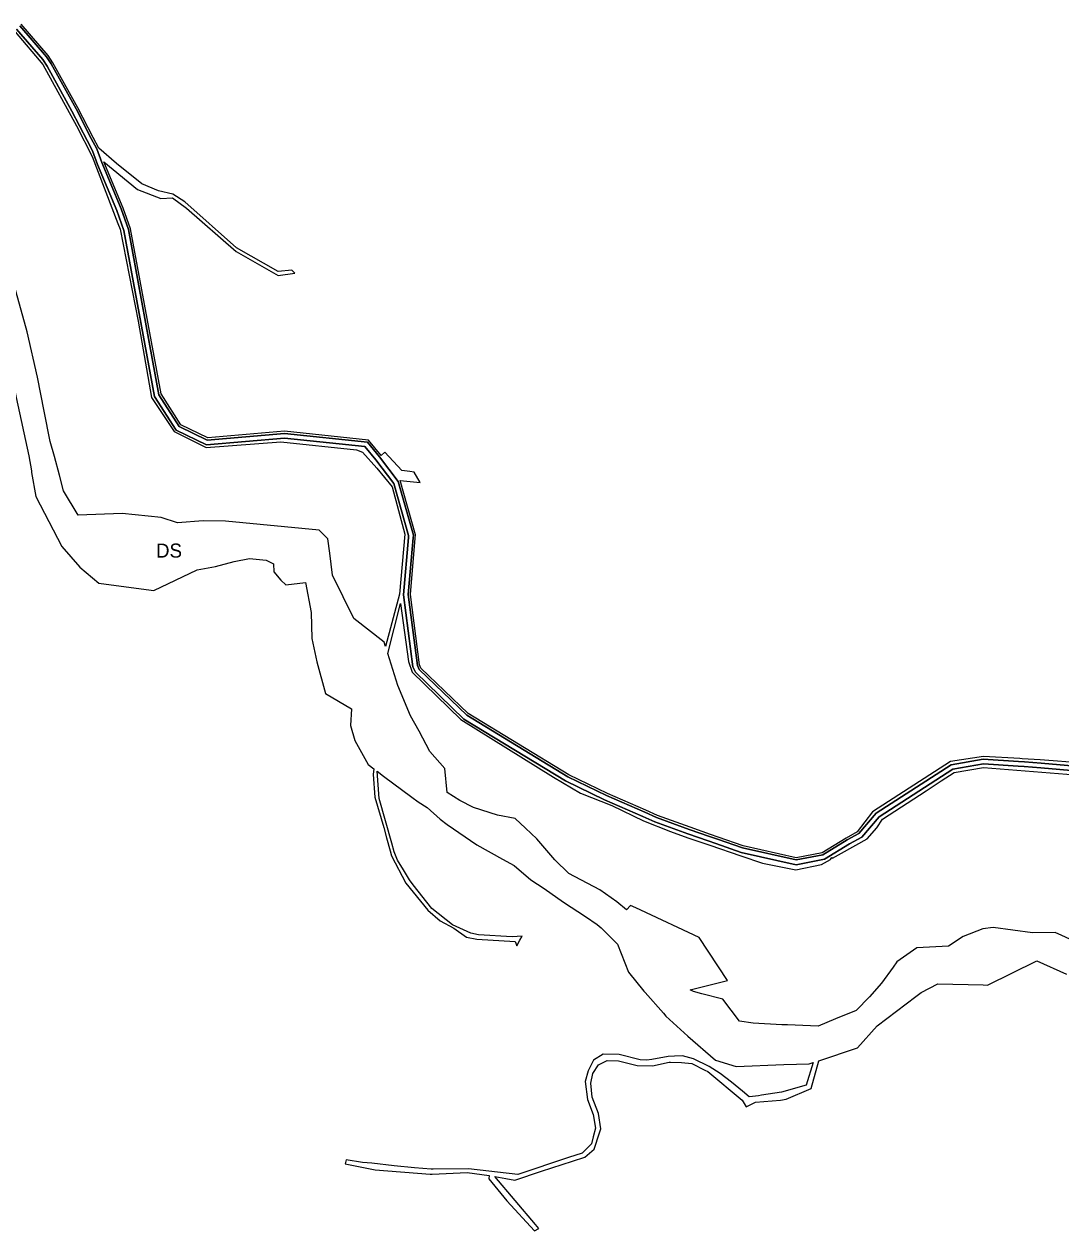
# Model space of a CAD drawing. Extents: x -477304 to -465641, y -1159113 to -1149285.
# Drawn here: x -476638 to -475972, y -1151586 to -1150812 of the extents above; entities that cross this region are included whole.
import ezdxf

# ---------------------------------------------------------------- set-up
doc = ezdxf.new("R2010")
doc.units = 0
doc.layers.add('14', color=7, linetype='Continuous')
doc.layers.add('35', color=7, linetype='Continuous')

msp = doc.modelspace()

# ---------------------------------------------------------------- linework, layer by layer
at = {"layer": '14'}
for points in [[(-476642.66, -1150814.82), (-476625.91, -1150834.23), (-476623.17, -1150838.54), (-476607.19, -1150867.39), (-476597.42, -1150886.27), (-476594.01, -1150892.86), (-476590.76, -1150901.49), (-476578.3, -1150931.21), (-476573.77, -1150944.02), (-476554.16, -1151050.43), (-476540.35, -1151072.15), (-476520.85, -1151081.51), (-476470.75, -1151077.16), (-476419.11, -1151082.62), (-476412.19, -1151090.99), (-476400.56, -1151106.27), (-476391.07, -1151139.73), (-476391.18, -1151140.91), (-476394.41, -1151177.66), (-476388.4, -1151223.93), (-476386.78, -1151227.31), (-476355.62, -1151257.4), (-476290.4, -1151297.08), (-476265.36, -1151309.27), (-476240.73, -1151319.97), (-476233.05, -1151323.47), (-476211.94, -1151331.01), (-476198.89, -1151335.55), (-476193.95, -1151337.27), (-476177.68, -1151342.98), (-476142.48, -1151350.92), (-476124.11, -1151347.34), (-476108.09, -1151337.56), (-476100.22, -1151333.1), (-476089.09, -1151320.18), (-476041.78, -1151289.56), (-476022.14, -1151286.25), (-475999.9, -1151287.63), (-475996.05, -1151287.84), (-475985.31, -1151288.74), (-475953.69, -1151291.49)], [(-475953.31, -1151288.51), (-475985.05, -1151285.75), (-475995.85, -1151284.85), (-475999.73, -1151284.64), (-476022.3, -1151283.24), (-476042.89, -1151286.71), (-476091.09, -1151317.9), (-476102.15, -1151330.75), (-476109.61, -1151334.97), (-476125.22, -1151344.5), (-476142.43, -1151347.85), (-476176.85, -1151340.09), (-476192.96, -1151334.44), (-476197.91, -1151332.72), (-476210.94, -1151328.18), (-476231.92, -1151320.68), (-476239.51, -1151317.23), (-476264.1, -1151306.55), (-476288.96, -1151294.44), (-476353.78, -1151255.01), (-476384.31, -1151225.53), (-476385.48, -1151223.07), (-476391.39, -1151177.6), (-476388.19, -1151141.18), (-476388.03, -1151139.44), (-476397.83, -1151104.9), (-476409.84, -1151089.13), (-476417.58, -1151079.77), (-476470.72, -1151074.15), (-476520.29, -1151078.45), (-476538.28, -1151069.81), (-476551.31, -1151049.31), (-476570.86, -1150943.24), (-476575.5, -1150930.13), (-476587.98, -1150900.39), (-476591.27, -1150891.64), (-476594.76, -1150884.89), (-476604.55, -1150865.98), (-476620.59, -1150837), (-476623.5, -1150832.43), (-476640.64, -1150812.58)]]:
    msp.add_lwpolyline(points, dxfattribs=at)
at = {"layer": '35'}
for p, q in [((-476622.38, -1150831.6), (-476639.7, -1150811.53)), ((-476643.54, -1150816.44), (-476625.93, -1150837.46)), ((-476619.39, -1150836.29), (-476622.38, -1150831.6)), ((-476625.93, -1150837.46), (-476604.19, -1150876.72)), ((-476603.32, -1150865.32), (-476619.39, -1150836.29)), ((-476593.52, -1150884.25), (-476603.32, -1150865.32)), ((-476589.99, -1150891.07), (-476593.52, -1150884.25)), ((-476578.66, -1150901.01), (-476589.99, -1150891.07)), ((-476574.2, -1150929.63), (-476586.68, -1150899.87)), ((-476586.68, -1150899.87), (-476565.05, -1150917.63)), ((-476562.32, -1150914.04), (-476578.66, -1150901.01)), ((-476565.05, -1150917.63), (-476550.04, -1150923.44)), ((-476534.64, -1150925.58), (-476542.51, -1150920.67)), ((-476474.84, -1150972.71), (-476464.02, -1150971.38)), ((-476466.14, -1150969.46), (-476474.78, -1150970.34)), ((-476464.02, -1150971.38), (-476466.14, -1150969.46)), ((-476556.1, -1151051.13), (-476541.51, -1151072.81)), ((-476537.32, -1151068.73), (-476549.99, -1151048.79)), ((-476541.51, -1151072.81), (-476520.92, -1151083.15)), ((-476520.03, -1151077.03), (-476537.32, -1151068.73)), ((-476470.71, -1151072.75), (-476520.03, -1151077.03)), ((-476416.87, -1151078.44), (-476470.71, -1151072.75)), ((-476520.92, -1151083.15), (-476473.05, -1151079.6)), ((-476473.05, -1151079.6), (-476424.55, -1151084.62)), ((-476408.75, -1151088.26), (-476416.87, -1151078.44)), ((-476634.92, -1151088.51), (-476633.21, -1151098.11)), ((-476424.55, -1151084.62), (-476420.69, -1151086.09)), ((-476420.69, -1151086.09), (-476411.49, -1151096.46)), ((-476406.46, -1151086.27), (-476408.75, -1151088.26)), ((-476395.44, -1151097.97), (-476406.46, -1151086.27)), ((-476633.21, -1151098.11), (-476633.02, -1151099.3)), ((-476411.49, -1151096.46), (-476401.66, -1151108.45)), ((-476390.38, -1151098.59), (-476395.44, -1151097.97)), ((-476396.56, -1151104.27), (-476383.64, -1151105.71)), ((-476387.56, -1151099.04), (-476390.38, -1151098.59)), ((-476383.64, -1151105.71), (-476387.56, -1151099.04)), ((-476574.84, -1151125.55), (-476603.1, -1151126.52)), ((-476441.63, -1151150.91), (-476443.04, -1151141.85)), ((-476439.9, -1151165.06), (-476441.63, -1151150.91)), ((-476554.67, -1151174.97), (-476526.86, -1151161.65)), ((-476477.6, -1151162.96), (-476473.1, -1151168.36)), ((-476426.36, -1151192.97), (-476439.9, -1151165.06)), ((-476396.99, -1151177.28), (-476405.87, -1151210.97)), ((-476404.5, -1151215.31), (-476396.2, -1151183.22)), ((-476396.2, -1151183.22), (-476391.22, -1151220.46)), ((-476398, -1151235.98), (-476404.5, -1151215.31)), ((-476383.16, -1151224.7), (-476384.13, -1151222.67)), ((-476352.92, -1151253.9), (-476383.16, -1151224.7)), ((-476288.29, -1151293.22), (-476352.92, -1151253.9)), ((-476428.34, -1151261.66), (-476425.69, -1151271.16)), ((-476377.58, -1151278.27), (-476384.43, -1151265.14)), ((-475985.84, -1151283.58), (-475997.32, -1151282.86)), ((-475958.11, -1151285.78), (-475985.84, -1151283.58)), ((-476413.42, -1151289.39), (-476413.77, -1151292.95)), ((-476410.09, -1151308.46), (-476411.36, -1151290.95)), ((-476263.52, -1151305.28), (-476288.29, -1151293.22)), ((-476059.04, -1151303.43), (-476049.41, -1151297.03)), ((-476049.41, -1151297.03), (-476041.07, -1151291.81)), ((-476086.94, -1151321.74), (-476059.04, -1151303.43)), ((-476401.85, -1151337.16), (-476410.09, -1151308.46)), ((-476385.07, -1151310.45), (-476379.17, -1151314.22)), ((-476379.17, -1151314.22), (-476370.84, -1151321.76)), ((-476316.03, -1151327.52), (-476322.68, -1151321.3)), ((-476240.43, -1151322.7), (-476223, -1151329.58)), ((-476093.34, -1151316.86), (-476103.13, -1151329.7)), ((-476090.63, -1151327.32), (-476086.94, -1151321.74)), ((-476407, -1151327.11), (-476405.24, -1151333.64)), ((-476223, -1151329.58), (-476211.87, -1151333.69)), ((-476103.13, -1151329.7), (-476110.32, -1151333.77)), ((-476096.81, -1151334.23), (-476090.63, -1151327.32)), ((-476400.45, -1151342.69), (-476401.85, -1151337.16)), ((-476347.32, -1151338.15), (-476330.92, -1151347.31)), ((-476176.46, -1151338.75), (-476192.5, -1151333.12)), ((-476110.32, -1151333.77), (-476125.73, -1151343.18)), ((-476113.38, -1151343.53), (-476096.81, -1151334.23)), ((-476402.11, -1151345.22), (-476392.86, -1151362.69)), ((-476398.2, -1151348.06), (-476400.45, -1151342.69)), ((-476177.91, -1151345.12), (-476164.06, -1151349.82)), ((-476118.96, -1151346.66), (-476113.38, -1151343.53)), ((-476394.48, -1151354.09), (-476398.2, -1151348.06)), ((-476330.92, -1151347.31), (-476323.3, -1151351.3)), ((-476288.27, -1151356.51), (-476297.23, -1151347.85)), ((-476126.17, -1151350.72), (-476120.34, -1151347.44)), ((-476120.34, -1151347.44), (-476119.45, -1151346.29)), ((-476119.45, -1151346.29), (-476118.96, -1151346.66)), ((-476390.45, -1151360.63), (-476394.48, -1151354.09)), ((-476388.16, -1151363.74), (-476390.45, -1151360.63)), ((-476268.39, -1151367.02), (-476288.27, -1151356.51)), ((-476392.86, -1151362.69), (-476378.85, -1151380.09)), ((-476376.2, -1151379), (-476388.16, -1151363.74)), ((-476257.41, -1151374.76), (-476268.39, -1151367.02)), ((-476251.27, -1151379.83), (-476257.41, -1151374.76)), ((-476378.85, -1151380.09), (-476370.78, -1151386.79)), ((-476204.63, -1151397.52), (-476241.99, -1151380.13)), ((-476370.78, -1151386.79), (-476362.02, -1151391.51)), ((-476362.02, -1151391.51), (-476353.92, -1151397.38)), ((-476269.99, -1151389.31), (-476267.58, -1151391.48)), ((-476267.58, -1151391.48), (-476256.99, -1151401.96)), ((-476022.58, -1151392.02), (-476035.16, -1151397.04)), ((-476015.93, -1151391.11), (-476022.58, -1151392.02)), ((-475990.68, -1151394.51), (-476015.93, -1151391.11)), ((-476353.92, -1151397.38), (-476347.4, -1151398.62)), ((-476346.23, -1151395.92), (-476351.16, -1151394.79)), ((-476347.4, -1151398.62), (-476322.81, -1151400.15)), ((-476324.71, -1151397.09), (-476346.23, -1151395.92)), ((-476318.23, -1151396.75), (-476324.71, -1151397.09)), ((-476322.81, -1151400.15), (-476321.73, -1151402.9)), ((-476321.73, -1151402.9), (-476319.71, -1151399.32)), ((-476319.71, -1151399.32), (-476318.23, -1151396.75)), ((-476186.54, -1151425.18), (-476204.63, -1151397.52)), ((-476035.16, -1151397.04), (-476044.6, -1151403.16)), ((-475976.2, -1151394.31), (-475990.68, -1151394.51)), ((-476044.6, -1151403.16), (-476064.85, -1151404.13)), ((-476019.56, -1151428.19), (-475987.82, -1151412.6)), ((-475987.82, -1151412.6), (-475968.79, -1151421.19)), ((-476080.18, -1151416.71), (-476087.65, -1151426.89)), ((-476210.37, -1151431.1), (-476186.54, -1151425.18)), ((-476087.65, -1151426.89), (-476095.31, -1151435.71)), ((-476062.2, -1151432.93), (-476051.5, -1151427.33)), ((-476051.5, -1151427.33), (-476022.39, -1151428.01)), ((-476022.39, -1151428.01), (-476019.56, -1151428.19)), ((-476239.19, -1151432.96), (-476227.53, -1151446.2)), ((-476095.31, -1151435.71), (-476103.94, -1151444.53)), ((-476090.46, -1151454.27), (-476065.48, -1151435.34)), ((-476065.48, -1151435.34), (-476062.2, -1151432.93)), ((-476227.53, -1151446.2), (-476226.06, -1151447.98)), ((-476226.06, -1151447.98), (-476211.83, -1151460.99)), ((-476147.99, -1151453.67), (-476151.51, -1151453.53)), ((-476103.12, -1151468.47), (-476090.46, -1151454.27)), ((-476211.83, -1151460.99), (-476194.04, -1151476.2)), ((-476127.89, -1151476.65), (-476103.12, -1151468.47)), ((-476256.05, -1151472.57), (-476266.21, -1151472.52)), ((-476208.33, -1151475.52), (-476215.41, -1151473.57)), ((-476198.28, -1151480.3), (-476208.33, -1151475.52)), ((-476194.04, -1151476.2), (-476180.86, -1151480.43)), ((-476275.76, -1151483.15), (-476277.8, -1151489.9)), ((-476200.95, -1151482.78), (-476199.05, -1151483.55)), ((-476199.05, -1151483.55), (-476176.95, -1151501.92)), ((-476277.8, -1151489.9), (-476276.37, -1151501.52)), ((-476273.25, -1151499.95), (-476274.2, -1151490.98)), ((-476176.8, -1151496.23), (-476183.89, -1151490.43)), ((-476269.33, -1151510.54), (-476273.25, -1151499.95)), ((-476172.47, -1151499.83), (-476176.8, -1151496.23)), ((-476170.33, -1151499.57), (-476172.47, -1151499.83)), ((-476151.85, -1151496.93), (-476164.64, -1151498.74)), ((-476276.37, -1151501.52), (-476272.64, -1151511.14)), ((-476176.95, -1151501.92), (-476174.52, -1151506.3)), ((-476174.52, -1151506.3), (-476168.48, -1151503.29)), ((-476168.48, -1151503.29), (-476152.35, -1151501.95)), ((-476152.35, -1151501.95), (-476148.83, -1151501.25)), ((-476273.68, -1151530), (-476279.66, -1151535.9)), ((-476272.55, -1151525.56), (-476273.68, -1151530)), ((-476288.41, -1151538.81), (-476320.96, -1151549.65)), ((-476279.66, -1151535.9), (-476288.41, -1151538.81)), ((-476285.88, -1151541.09), (-476277.94, -1151538.48)), ((-476431.07, -1151540.31), (-476431.91, -1151542.86)), ((-476431.91, -1151542.86), (-476412.65, -1151546.62)), ((-476400.35, -1151544.17), (-476414.78, -1151542.4)), ((-476412.65, -1151546.62), (-476377.17, -1151549.4)), ((-476387.24, -1151545.36), (-476400.35, -1151544.17)), ((-476376.66, -1151546.28), (-476387.24, -1151545.36)), ((-476375.28, -1151546.27), (-476376.66, -1151546.28)), ((-476352.56, -1151546.07), (-476375.28, -1151546.27)), ((-476320.96, -1151549.65), (-476352.56, -1151546.07)), ((-476377.17, -1151549.4), (-476375.97, -1151549.35)), ((-476375.97, -1151549.35), (-476353.46, -1151548.47)), ((-476353.46, -1151548.47), (-476339.44, -1151550.28)), ((-476339.44, -1151550.28), (-476339.71, -1151552.33)), ((-476339.71, -1151552.33), (-476327.96, -1151566.52)), ((-476335.79, -1151551), (-476328.8, -1151552.22)), ((-476328.8, -1151552.22), (-476322.91, -1151553.24)), ((-476327.96, -1151566.52), (-476310.28, -1151585.82)), ((-476310.28, -1151585.82), (-476307.47, -1151584.26))]:
    msp.add_line(p, q, dxfattribs=at)
for points in [[(-475953.69, -1151291.49), (-475985.31, -1151288.74), (-475996.05, -1151287.84), (-475999.9, -1151287.63), (-476022.14, -1151286.25), (-476041.78, -1151289.56), (-476089.09, -1151320.18), (-476100.22, -1151333.1), (-476108.09, -1151337.56), (-476124.11, -1151347.34), (-476142.48, -1151350.92), (-476177.68, -1151342.98), (-476193.95, -1151337.27), (-476198.89, -1151335.55), (-476211.94, -1151331.01), (-476233.05, -1151323.47), (-476240.73, -1151319.97), (-476265.36, -1151309.27), (-476290.4, -1151297.08), (-476355.62, -1151257.4), (-476386.78, -1151227.31), (-476388.4, -1151223.93), (-476394.41, -1151177.66), (-476391.18, -1151140.91), (-476391.07, -1151139.73), (-476400.56, -1151106.27), (-476412.19, -1151090.99), (-476419.11, -1151082.62), (-476470.75, -1151077.16), (-476520.85, -1151081.51), (-476540.35, -1151072.15), (-476554.16, -1151050.43), (-476573.77, -1150944.02), (-476578.3, -1150931.21), (-476590.76, -1150901.49), (-476594.01, -1150892.86), (-476597.42, -1150886.27), (-476607.19, -1150867.39), (-476623.17, -1150838.54), (-476625.91, -1150834.23), (-476642.66, -1150814.82)], [(-476640.64, -1150812.58), (-476623.5, -1150832.43), (-476620.59, -1150837), (-476604.55, -1150865.98), (-476594.76, -1150884.89), (-476591.27, -1150891.64), (-476587.98, -1150900.39), (-476575.5, -1150930.13), (-476570.86, -1150943.24), (-476551.31, -1151049.31), (-476538.28, -1151069.81), (-476520.29, -1151078.45), (-476470.72, -1151074.15), (-476417.58, -1151079.77), (-476409.84, -1151089.13), (-476397.83, -1151104.9), (-476388.03, -1151139.44), (-476388.19, -1151141.18), (-476391.39, -1151177.6), (-476385.48, -1151223.07), (-476384.31, -1151225.53), (-476353.78, -1151255.01), (-476288.96, -1151294.44), (-476264.1, -1151306.55), (-476239.51, -1151317.23), (-476231.92, -1151320.68), (-476210.94, -1151328.18), (-476197.91, -1151332.72), (-476192.96, -1151334.44), (-476176.85, -1151340.09), (-476142.43, -1151347.85), (-476125.22, -1151344.5), (-476109.61, -1151334.97), (-476102.15, -1151330.75), (-476091.09, -1151317.9), (-476042.89, -1151286.71), (-476022.3, -1151283.24), (-475999.73, -1151284.64), (-475995.85, -1151284.85), (-475985.05, -1151285.75), (-475953.31, -1151288.51)], [(-476604.19, -1150876.72), (-476594.1, -1150896.54), (-476577.61, -1150939.37)], [(-476636, -1151008.86), (-476647.34, -1150968.02), (-476653.08, -1150937.24), (-476658.4, -1150918.61), (-476665.53, -1150903.88), (-476677.04, -1150890.53), (-476687.72, -1150882.23)], [(-476542.51, -1150920.67), (-476551.55, -1150918.49), (-476562.32, -1150914.04)], [(-476550.04, -1150923.44), (-476542.72, -1150923.05), (-476533.57, -1150929.63)], [(-476474.78, -1150970.34), (-476501.6, -1150954.99), (-476534.64, -1150925.58)], [(-476549.99, -1151048.79), (-476569.51, -1150942.88), (-476574.2, -1150929.63)], [(-476533.57, -1150929.63), (-476501.81, -1150957.48), (-476474.84, -1150972.71)], [(-476577.61, -1150939.37), (-476576.17, -1150943.01), (-476564.69, -1151002.06), (-476556.1, -1151051.13)], [(-476618.45, -1151088.97), (-476621.14, -1151079.33), (-476625.08, -1151059.78), (-476629.32, -1151038.09), (-476636, -1151008.86)], [(-476649.25, -1151018.99), (-476643, -1151051.19), (-476634.92, -1151088.51)], [(-476603.1, -1151126.52), (-476612.48, -1151110.96), (-476615.15, -1151100.89), (-476618.45, -1151088.97)], [(-476633.02, -1151099.3), (-476630.34, -1151114.57), (-476613.58, -1151146.77)], [(-476384.13, -1151222.67), (-476389.99, -1151177.57), (-476386.8, -1151141.3), (-476386.62, -1151139.31), (-476396.56, -1151104.27)], [(-476401.66, -1151108.45), (-476393.53, -1151138.82), (-476396.99, -1151177.28)], [(-476539.37, -1151131.41), (-476549.87, -1151128.09), (-476574.84, -1151125.55)], [(-476508.69, -1151130.43), (-476522.88, -1151130.26), (-476539.37, -1151131.41)], [(-476443.04, -1151141.85), (-476448.6, -1151136.17), (-476508.69, -1151130.43)], [(-476613.58, -1151146.77), (-476602.07, -1151159.87), (-476589.97, -1151170.16)], [(-476526.86, -1151161.65), (-476514.97, -1151159.5), (-476503.09, -1151156.42), (-476493.27, -1151154.3), (-476482.43, -1151155.5)], [(-476482.43, -1151155.5), (-476477.83, -1151157.79), (-476477.6, -1151162.96)], [(-476589.97, -1151170.16), (-476572.29, -1151172.48), (-476554.67, -1151174.97)], [(-476473.1, -1151168.36), (-476469.87, -1151171.32), (-476457.18, -1151169.82), (-476453.72, -1151189.09), (-476453.26, -1151205.74), (-476449.91, -1151220.65), (-476444.49, -1151241.07), (-476427.71, -1151250.94), (-476428.34, -1151261.66)], [(-476405.87, -1151210.97), (-476406.8, -1151208.03), (-476426.36, -1151192.97)], [(-476391.22, -1151220.46), (-476388.74, -1151227.24), (-476357.6, -1151257.79), (-476298.14, -1151294.63)], [(-476384.43, -1151265.14), (-476389.94, -1151255.37), (-476398, -1151235.98)], [(-476425.69, -1151271.16), (-476417.13, -1151286.58), (-476413.42, -1151289.39)], [(-476349.46, -1151314.1), (-476358.25, -1151309.7), (-476366.28, -1151304.61), (-476367.84, -1151289.16), (-476377.58, -1151278.27)], [(-476022.09, -1151281.47), (-476043.4, -1151284.69), (-476093.34, -1151316.86)], [(-475997.32, -1151282.86), (-475998.91, -1151282.76), (-476022.09, -1151281.47)], [(-476411.36, -1151290.95), (-476407.27, -1151294.05), (-476389.12, -1151307.46), (-476385.07, -1151310.45)], [(-476041.07, -1151291.81), (-476022.25, -1151288.41), (-475952.66, -1151294), (-475935.11, -1151296.91)], [(-476413.77, -1151292.95), (-476412.79, -1151307.45), (-476407, -1151327.11)], [(-476298.14, -1151294.63), (-476280.74, -1151305.08), (-476260.76, -1151312.82), (-476240.43, -1151322.7)], [(-476192.5, -1151333.12), (-476197.45, -1151331.4), (-476210.48, -1151326.87), (-476231.4, -1151319.39), (-476238.94, -1151315.96), (-476263.52, -1151305.28)], [(-476322.68, -1151321.3), (-476334.08, -1151319.06), (-476349.46, -1151314.1)], [(-476370.84, -1151321.76), (-476366.25, -1151325.05), (-476347.32, -1151338.15)], [(-476297.23, -1151347.85), (-476308.83, -1151334.25), (-476316.03, -1151327.52)], [(-476405.24, -1151333.64), (-476402.98, -1151342.02), (-476402.11, -1151345.22)], [(-476211.87, -1151333.69), (-476197.68, -1151338.41), (-476177.91, -1151345.12)], [(-476125.73, -1151343.18), (-476142.41, -1151346.43), (-476176.46, -1151338.75)], [(-476323.3, -1151351.3), (-476312.68, -1151360.57), (-476304.1, -1151366.18), (-476291.73, -1151374.88), (-476277.51, -1151384.04), (-476269.99, -1151389.31)], [(-476164.06, -1151349.82), (-476142.61, -1151354.27), (-476126.17, -1151350.72)], [(-476351.16, -1151394.79), (-476362.93, -1151389.4), (-476376.2, -1151379)], [(-476241.99, -1151380.13), (-476245.33, -1151378.56), (-476248.76, -1151377.11), (-476251.27, -1151379.83)], [(-475961.59, -1151401.01), (-475971.81, -1151396.32), (-475976.2, -1151394.31)], [(-476256.99, -1151401.96), (-476249.88, -1151419.91), (-476240.05, -1151431.98), (-476239.19, -1151432.96)], [(-476064.85, -1151404.13), (-476077.72, -1151413.24), (-476080.18, -1151416.71)], [(-476151.51, -1151453.53), (-476169.97, -1151452.53), (-476178.8, -1151451.27), (-476189.49, -1151437.15), (-476202.97, -1151433.65), (-476208.23, -1151432.28), (-476210.37, -1151431.1)], [(-476103.94, -1151444.53), (-476117.15, -1151449.84), (-476128.34, -1151454.57), (-476147.99, -1151453.67)], [(-476266.21, -1151472.52), (-476272.41, -1151476.22), (-476275.76, -1151483.15)], [(-476269.17, -1151479.28), (-476263.58, -1151476.59), (-476256.44, -1151476.71), (-476244.43, -1151479.68)], [(-476238.32, -1151476.23), (-476242.47, -1151476.08), (-476256.05, -1151472.57)], [(-476244.43, -1151479.68), (-476234.5, -1151479.89), (-476223.91, -1151477.59), (-476223.01, -1151477.62)], [(-476215.41, -1151473.57), (-476220.43, -1151473.78), (-476224.5, -1151473.95), (-476235.04, -1151475.81), (-476238.32, -1151476.23)], [(-476223.01, -1151477.62), (-476215.89, -1151477.84), (-476209.38, -1151478.37), (-476200.95, -1151482.78)], [(-476148.83, -1151501.25), (-476132.77, -1151494.37), (-476127.89, -1151476.65)], [(-476274.2, -1151490.98), (-476272.78, -1151484.81), (-476269.17, -1151479.28)], [(-476183.89, -1151490.43), (-476191.16, -1151484.85), (-476198.28, -1151480.3)], [(-476180.86, -1151480.43), (-476150.27, -1151479.13), (-476134.05, -1151478.67), (-476131.37, -1151477.85)], [(-476131.37, -1151477.85), (-476136.04, -1151492.37), (-476151.85, -1151496.93)], [(-476164.64, -1151498.74), (-476166.57, -1151499.18), (-476170.33, -1151499.57)], [(-476277.94, -1151538.48), (-476271.98, -1151533.3), (-476268.56, -1151522.88), (-476267.72, -1151520.32), (-476269.33, -1151510.54)], [(-476272.64, -1151511.14), (-476271.12, -1151519.95), (-476272.55, -1151525.56)], [(-476414.78, -1151542.4), (-476420.76, -1151541.86), (-476431.07, -1151540.31)], [(-476322.91, -1151553.24), (-476305.74, -1151547.61), (-476285.88, -1151541.09)], [(-476307.47, -1151584.26), (-476309.58, -1151581.76), (-476335.79, -1151551)]]:
    msp.add_lwpolyline(points, dxfattribs=at)

# ---------------------------------------------------------------- texts
msp.add_text('DS', height=9, dxfattribs=at).set_placement((-476553.24, -1151153.82))

doc.saveas('drawing.dxf')
